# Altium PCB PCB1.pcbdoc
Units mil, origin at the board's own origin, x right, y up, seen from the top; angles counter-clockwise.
Board outline 2142.5 x 2720 mil, 2 copper layers (Top Layer, Bottom Layer); 27 components, 29 nets, 158 pads, 29 vias.
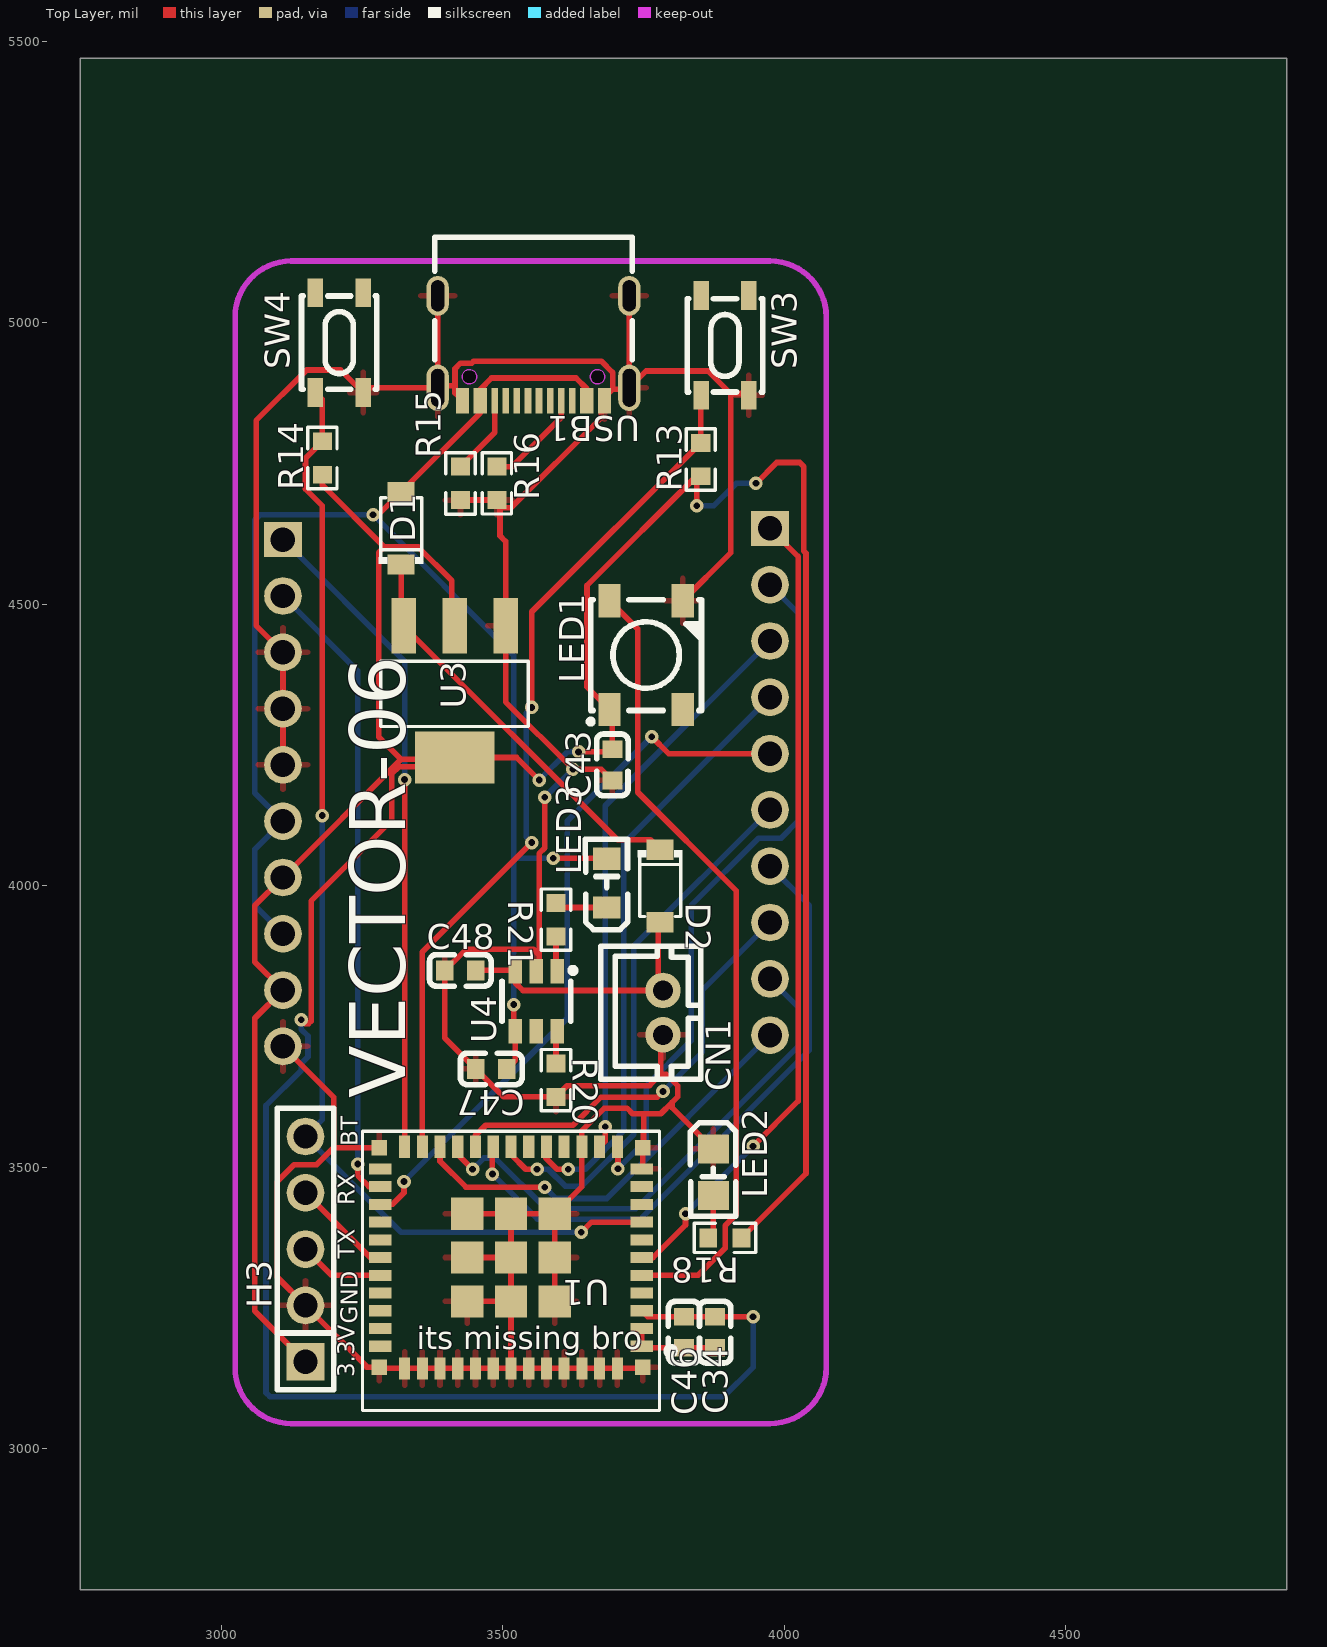
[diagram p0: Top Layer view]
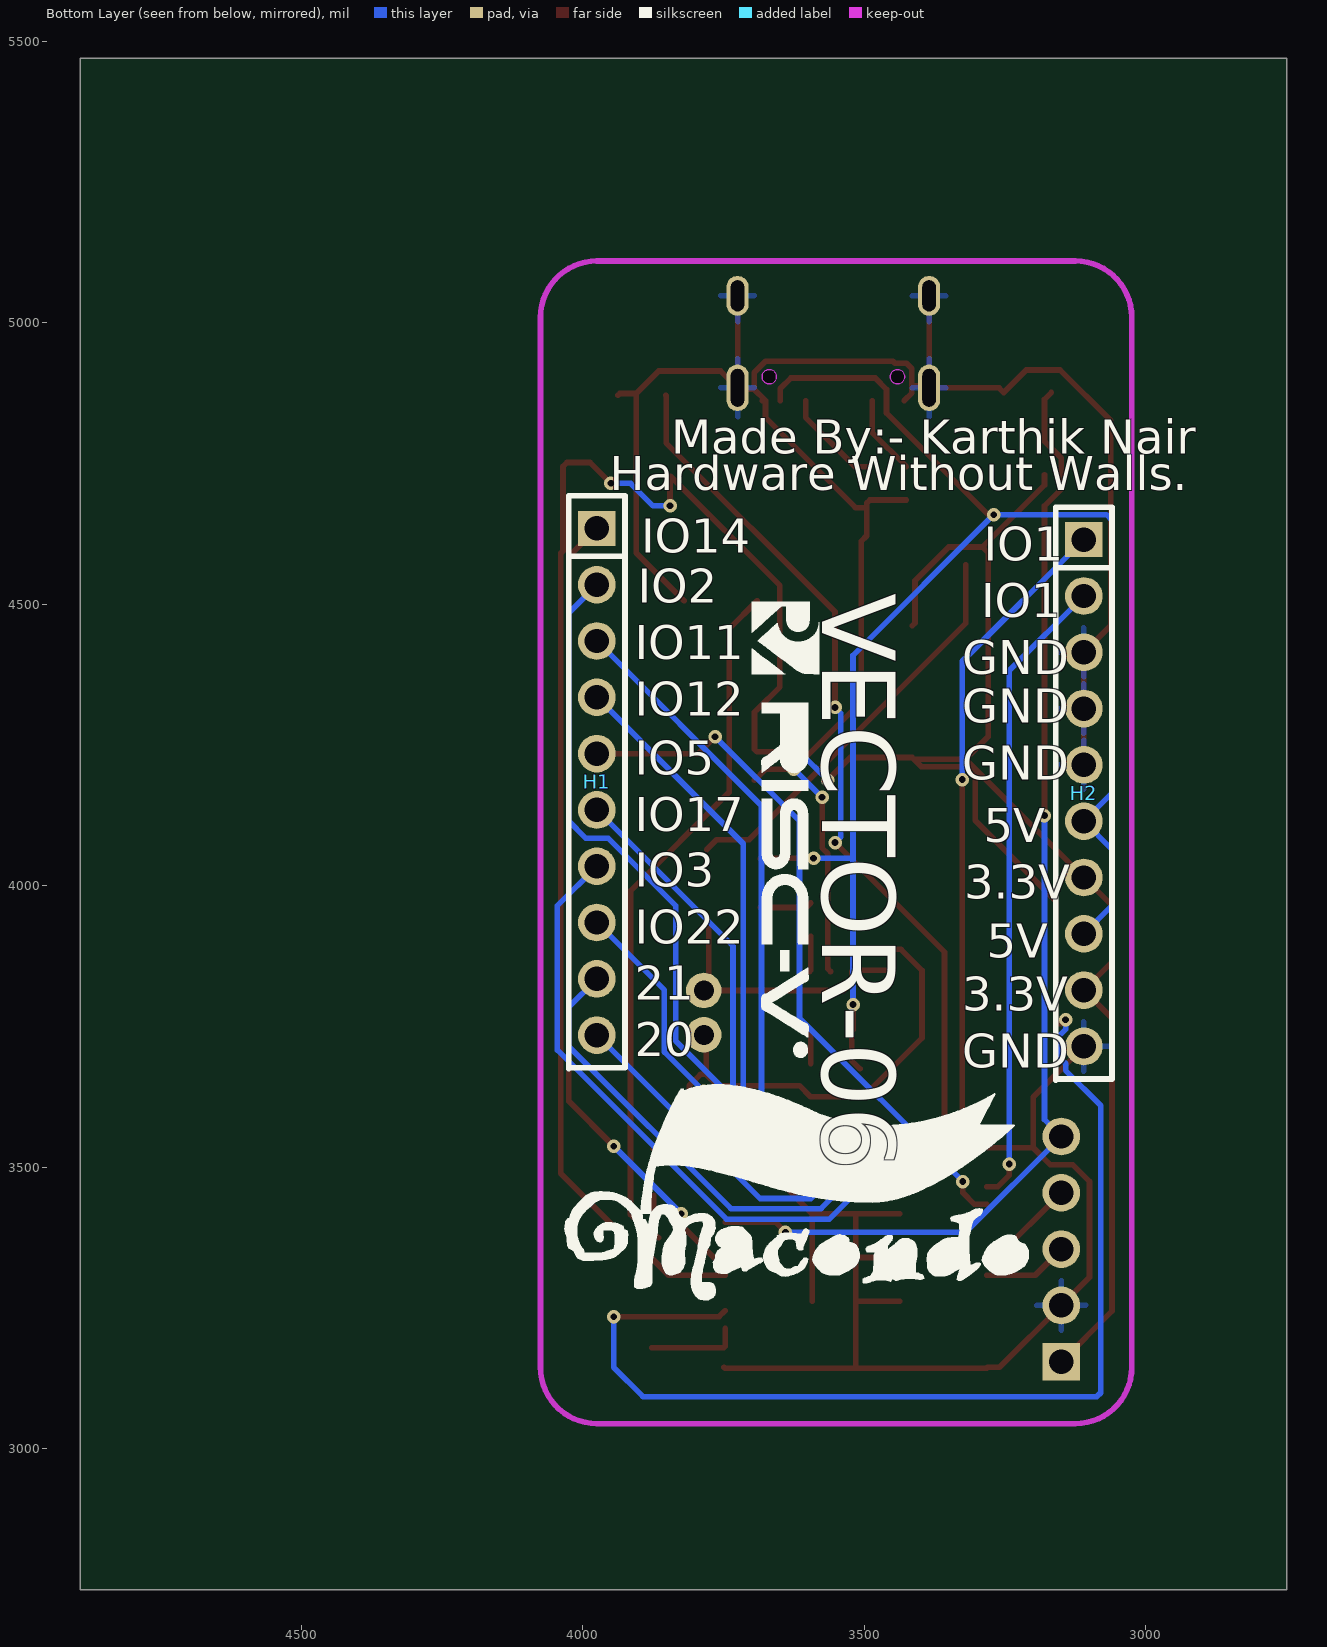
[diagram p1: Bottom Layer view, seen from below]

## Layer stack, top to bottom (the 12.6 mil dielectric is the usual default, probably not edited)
Top Layer: signal copper (thickness not stored)
Dielectric: dielectric 12.6, FR-4, Dk 4.8
Bottom Layer: signal copper (thickness not stored)

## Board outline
4892.5,2750 2750,2750 2750,5470 4892.5,5470

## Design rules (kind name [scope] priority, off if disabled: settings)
BoardOutlineClearance copperThickness1oz [All] p0: genericclearance=10 ignorepadtopadclearanceinfootprint=FALSE except(0: Arc-SplitContinuation Track-SplitContinuation SMDPad-SplitContinuation THPad-SplitContinuation Via-SplitContinuation Fill-SplitContinuation Poly-SplitContinuation Region-SplitContinuation Text-SplitContinuation; 6: Track-CutoutEdge SMDPad-CutoutEdge THPad-CutoutEdge Via-CutoutEdge Region-CutoutEdge; 11.8: Track-OutlineEdge SMDPad-OutlineEdge THPad-OutlineEdge Via-OutlineEdge Fill-OutlineEdge Region-OutlineEdge Poly-OutlineEdge Text-OutlineEdge Fill-CutoutEdge)
BoardOutlineClearance copperThickness2oz [All] p0: genericclearance=10 ignorepadtopadclearanceinfootprint=FALSE except(0: Arc-SplitContinuation Track-SplitContinuation SMDPad-SplitContinuation THPad-SplitContinuation Via-SplitContinuation Fill-SplitContinuation Poly-SplitContinuation Region-SplitContinuation Text-SplitContinuation; 6: Track-CutoutEdge SMDPad-CutoutEdge THPad-CutoutEdge Via-CutoutEdge Region-CutoutEdge; 11.8: Track-OutlineEdge SMDPad-OutlineEdge THPad-OutlineEdge Via-OutlineEdge Fill-OutlineEdge Region-OutlineEdge Poly-OutlineEdge Text-OutlineEdge Fill-CutoutEdge)
Clearance copperThickness1oz [(InNet('$1N1250') OR InNet('VCC') OR InNet('GND') OR InNet('+5V') OR InNet('IO20') OR InNet('IO21') OR InNet('IO22') OR InNet('IO3') OR InNet('IO17') OR InNet('IO5') OR InNet('IO12') OR InNet('IO11') OR InNet('IO2') OR InNet('IO14') OR InNet('IO1') OR InNet('IO0') OR InNet('TXD') OR InNet('RXD') OR InNet('BOOT_PIN') OR InNet('LED_PIN_RGB') OR InNet('$1N5981') OR InNet('NRST') OR InNet('$1N2534') OR InNet('$1N2536') OR InNet('V_REG_IN') OR InNet('BAT+') OR InNet('$1N8604') OR InNet('$1N8891') OR InNet('$1N8602'))] p1: gap=7 ignorepadtopadclearanceinfootprint=FALSE except(4: Track-Track; 6: Track-SMDPad SMDPad-SMDPad Track-THPad SMDPad-THPad THPad-THPad Track-Via SMDPad-Via THPad-Via Via-Via SMDPad-Fill THPad-Fill Via-Fill Fill-Fill Track-Region SMDPad-Region THPad-Region Via-Region Region-Region Track-Poly SMDPad-Poly THPad-Poly Via-Poly Fill-Poly Region-Poly Poly-Poly Track-Text SMDPad-Text THPad-Text Via-Text Fill-Text Region-Text Poly-Text Text-Text; 6.9: Track-Hole SMDPad-Hole THPad-Hole Via-Hole Fill-Hole Region-Hole Poly-Hole Text-Hole Sheet-Hole; 11.8: Track-Fill Fill-Region Track-Sheet SMDPad-Sheet THPad-Sheet Via-Sheet Fill-Sheet Region-Sheet Poly-Sheet Text-Sheet)
Clearance copperThickness2oz [All] p1: gap=7 ignorepadtopadclearanceinfootprint=FALSE except(6: Track-SMDPad SMDPad-SMDPad Track-THPad SMDPad-THPad THPad-THPad Track-Via SMDPad-Via THPad-Via Via-Via SMDPad-Fill THPad-Fill Via-Fill Fill-Fill Track-Region SMDPad-Region THPad-Region Via-Region Region-Region Track-Poly SMDPad-Poly THPad-Poly Via-Poly Fill-Poly Region-Poly Poly-Poly Track-Text SMDPad-Text THPad-Text Via-Text Fill-Text Region-Text Poly-Text Text-Text; 6.9: Track-Hole SMDPad-Hole THPad-Hole Via-Hole Fill-Hole Region-Hole Poly-Hole Text-Hole Sheet-Hole; 8: Track-Track; 11.8: Track-Fill Fill-Region Track-Sheet SMDPad-Sheet THPad-Sheet Via-Sheet Fill-Sheet Region-Sheet Poly-Sheet Text-Sheet)
DiffPairsRouting differentialPair [All] p1: maxuncoupledlength=10 minlimit=6 maxlimit=6 mostfreqgap=6 toplayer_minwidth=5 toplayer_prefwidth=10 toplayer_maxwidth=100 bottomlayer_minwidth=5 bottomlayer_prefwidth=10 bottomlayer_maxwidth=100
PasteMaskExpansion pasteMaskExpansion [All] p1: expansion=0
PlaneConnect innerPlane [All] p1: planeconnectstyle=Relief reliefexpansion=20 reliefentries=4 reliefconductorwidth=10 reliefairgap=10
PolygonConnect copperRegion [All] p1: connectstyle=Relief reliefentries=4 reliefconductorwidth=10 polygonreliefangle="90 Angle" airgapwidth=10
RoutingVias viaSize [All] p1: viastyle="Through Hole" holewidth=12.0078 minholewidth=11.811 maxholewidth=248.0314 width=24.0158 minwidth=19.685 maxwidth=393.7008
SolderMaskExpansion solderMaskExpansion [All] p1: useseparateexpansions=TRUE expansion=2 expansionbottom=2
Width copperThickness1oz [All] p1: maxlimit=100 minlimit=5 preferedwidth=10
Width copperThickness2oz [All] p1: maxlimit=100 minlimit=8 preferedwidth=10

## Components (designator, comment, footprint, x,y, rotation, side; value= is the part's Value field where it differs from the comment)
C34 "FCC0603B104K500CT" C0603 3877.5,3207.5 r270 top
C43 "FCC0603B104K500CT" C0603 3695,4215 r90 top
C46 "CGA0603X5R105K500JT" C0603 3822.5,3207.5 r90 top
C47 "TCC0603X5R475K160CT" C0603 3480,3675 r180 top
C48 "TCC0603X5R106K100CT" C0603 3425,3850 r0 top
CN1 "XY-B2B-PH-K-S" CONN-TH_B2B-PH-K-S 3785,3775 r90 top
D1 "1N5819W_C41431973" SOD-123_L2.7-W1.6-LS3.7-RD 3320,4635 r90 top
D2 "1N5819W_C41431973" SOD-123_L2.7-W1.6-LS3.7-RD 3780,4000 r270 top
H1 "2.54-1*10" HDR-TH_10P-P2.54-V-M 3975,4185 r270 bottom
H2 "2.54-1*10" HDR-TH_10P-P2.54-V-M 3110,4165 r270 bottom
H3 "2.54-1*5" HDR-TH_5P-P2.54-V-M 3150,3355 r90 top
LED1 "WS2812B-B/T" LED-SMD_4P-L5.0-W5.0-TL_WS2812B-B 3755,4410 r90 top
LED2 "YLED0805G" LED0805-FD-GREEN 3874.27,3491.65 r90 top
LED3 "YLED0805B" LED0805-RD 3685,4005 r90 top
R13 "FRC0603J103 TS" R0603 3851.97,4757.28 r90 top
R14 "FRC0603J103 TS" R0603 3180,4760 r90 top
R15 "FRC0603F5101TS" R0603 3425.29,4714.96 r90 top
R16 "FRC0603F5101TS" R0603 3490,4715 r90 top
R18 "FRC0603J331 TS" R0603 3895,3375 r180 top
R20 "FRC0603F2401TS" R0603 3595,3655 r270 top
R21 "FRC0603J102 TS" R0603 3595,3940 r270 top
SW3 "TS-1089S-02526" SW-SMD_4P-L4.2-W3.3-P2.15-LS5.1 3895,4960 r90 top
SW4 "TS-1089S-02526" SW-SMD_4P-L4.2-W3.3-P2.15-LS5.1 3210,4965 r90 top
U1 "Ai-WB2-M1-I" WIFIM-SMD_61P-CUSTOMBRUH 3515,3340 r180 top
U3 "AMS1117-3.3_C22459274" SOT-223-3_L6.5-W3.4-P2.30-LS7.0-BR-1 3415,4345 r90 top
U4 "TP4059" SOT-23-6_L2.9-W1.6-P0.95-LS2.8-BR 3560,3795 r90 top
USB1 "TYPE-C16PIN" USB-C-SMD_TYPE-C16PIN 3555,4955 r180 top

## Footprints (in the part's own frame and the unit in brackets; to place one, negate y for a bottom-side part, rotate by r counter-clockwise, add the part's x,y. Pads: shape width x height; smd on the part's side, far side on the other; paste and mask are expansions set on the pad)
C0603 [mm]
  rect 0.8x0.9 smd: 1(-0.7,0) 2(0.7,0)
  silkscreen extent -1.39,-0.71 1.39,0.71
CONN-TH_B2B-PH-K-S [mm]
  round 1.6 hole 0.9: 1(1,0) 2(-1,0)
  silkscreen extent -3,-1.7 3,2.8
HDR-TH_5P-P2.54-V-M [mm]
  rect 1.7x1.7 hole 1.1: 1(-5.08,0)
  round 1.7 hole 1.1: 2(-2.54,0) 3(0,0) 4(2.54,0) 5(5.08,0)
  silkscreen extent -6.35,-1.27 6.35,1.27
HDR-TH_10P-P2.54-V-M [mm]
  rect 1.575x1.7 hole 1.1: 1(-11.43,0)
  round 1.7 hole 1.1: 2(-8.89,0) 3(-6.35,0) 4(-3.81,0) 5(-1.27,0) 6(1.27,0) 7(3.81,0) 8(6.35,0) 9(8.89,0) 10(11.43,0)
  silkscreen extent -12.9,-1.27 12.95,1.27
LED0805-FD-GREEN [mil]
  rect 51.2x55.1 smd: 1(-41.35,0) 2(41.35,0)
  silkscreen extent -78,-40 88,41
LED0805-RD [mm]
  rect 1x1.25 smd: 1(-1.1,0) 2(1.1,0)
  silkscreen extent -2.1,-0.95 1.98,0.96
LED-SMD_4P-L5.0-W5.0-TL_WS2812B-B [mm]
  rect 1.5x1 smd: 1(-2.45,1.65) 2(-2.45,-1.65) 3(2.45,-1.65) 4(2.45,1.65)
  silkscreen extent -3.1,-2.5 2.5,2.6
R0603 [mil]
  rect 31.75x34.02 smd: 1(-29.66,0) 2(29.66,0)
  silkscreen extent -55,-26 55,26
SOD-123_L2.7-W1.6-LS3.7-RD [mm]
  rect 0.91x1.22 smd: 1(-1.635,0) 2(1.635,0)
  silkscreen extent -1.6,-1 1.38,1
SOT-23-6_L2.9-W1.6-P0.95-LS2.8-BR [mm]
  rect 1.1x0.6 smd: 1(1.35,-0.95) 2(1.35,0) 3(1.35,0.95) 4(-1.35,0.95) 5(-1.35,0) 6(-1.35,-0.95)
  silkscreen extent -0.9,-1.78 1.52,1.55
SOT-223-3_L6.5-W3.4-P2.30-LS7.0-BR-1 [mm]
  rect 2.5x1.1 smd: 1(2.97,-2.3) 2(2.97,0) 3(2.97,2.3)
  rect 2.34x3.6 smd: 2(-2.97,0)
  silkscreen extent -1.57,-3.33 1.37,3.33
SW-SMD_4P-L4.2-W3.3-P2.15-LS5.1 [mm]
  rect 1.3x0.7 smd: 1(-2.25,1.075) 2(2.25,1.075) 3(-2.25,-1.075) 4(2.25,-1.075)
  silkscreen extent -2.1,-1.7 2.1,1.7
USB-C-SMD_TYPE-C16PIN [mm]
  oval 1x2.1 hole 0.6 slot 1.7 at 90 deg: 1(-4.32,1.787) 2(4.32,1.787)
  oval 1x1.8 hole 0.6 slot 1.4 at 90 deg: 3(-4.32,-2.362) 4(4.32,-2.362)
  rect 0.6x1.15 smd: A1B12(-3.2,2.362) A4B9(-2.4,2.362) B1A12(3.2,2.362) B4A9(2.4,2.362)
  rect 0.3x1.15 smd: A5(-1.25,2.362) A6(-0.25,2.362) A7(0.25,2.362) A8(1.25,2.362) B5(1.75,2.362) B6(0.75,2.362) B7(-0.75,2.362) B8(-1.75,2.362)
  Board Outline Layer circle w0.005: c2.89,1.288 r0.325
  Board Outline Layer circle w0.005: c-2.89,1.288 r0.325
  Board Outline Layer region: 2.565,1.288 2.597,1.429 2.687,1.542 2.818,1.605 2.962,1.605 3.093,1.542 3.183,1.429 3.215,1.288 3.215,1.288 3.183,1.147 3.093,1.034 2.962,0.971 2.818,0.971 2.687,1.034 2.597,1.147 2.565,1.288
  Board Outline Layer region: -3.215,1.288 -3.183,1.429 -3.093,1.542 -2.962,1.605 -2.818,1.605 -2.687,1.542 -2.597,1.429 -2.565,1.288 -2.565,1.288 -2.597,1.147 -2.687,1.034 -2.818,0.971 -2.962,0.971 -3.093,1.034 -3.183,1.147 -3.215,1.288
  Multi-Layer board cut-out: 2.565,1.288 2.597,1.429 2.687,1.542 2.818,1.605 2.962,1.605 3.093,1.542 3.183,1.429 3.215,1.288 3.215,1.288 3.183,1.147 3.093,1.034 2.962,0.971 2.818,0.971 2.687,1.034 2.597,1.147 2.565,1.288
  Multi-Layer board cut-out: -3.215,1.288 -3.183,1.429 -3.093,1.542 -2.962,1.605 -2.818,1.605 -2.687,1.542 -2.597,1.429 -2.565,1.288 -2.565,1.288 -2.597,1.147 -2.687,1.034 -2.818,0.971 -2.962,0.971 -3.093,1.034 -3.183,1.147 -3.215,1.288
  silkscreen extent -4.45,-5 4.45,0.52
WIFIM-SMD_61P-CUSTOMBRUH [mm]
  rect 1x0.5 smd: 1(-5.9,4) 2(-5.9,3.2) 3(-5.9,2.4) 4(-5.9,1.6) 5(-5.9,0.8) 6(-5.9,0) 7(-5.9,-0.8) 8(-5.9,-1.6) 9(-5.9,-2.4) 10(-5.9,-3.2) 11(-5.9,-4) 25(5.9,-4) 26(5.9,-3.2) 27(5.9,-2.4) 28(5.9,-1.6) 29(5.9,-0.8) 30(5.9,0) 31(5.9,0.8) 32(5.9,1.6) 33(5.9,2.4) 34(5.9,3.2) 35(5.9,4)
  rect 0.5x1 smd: 12(-4.8,-5) 13(-4,-5) 14(-3.2,-5) 15(-2.4,-5) 16(-1.6,-5) 17(-0.8,-5) 18(0,-5) 19(0.8,-5) 20(1.6,-5) 21(2.4,-5) 22(3.2,-5) 23(4,-5) 24(4.8,-5) 36(4.8,5) 37(4,5) 38(3.2,5) 39(2.4,5) 40(1.6,5) 41(0.8,5) 42(0,5) 43(-0.8,5) 44(-1.6,5) 45(-2.4,5) 46(-3.2,5) 47(-4,5) 48(-4.8,5)
  rect 1.45x1.45 smd: 49(0,0) 54(-1.975,0) 55(-1.975,1.975) 56(0,1.975) 57(1.975,1.975) 58(1.975,0) 59(-1.975,-1.975) 60(0,-1.975) 61(1.975,-1.975)
  rect 0.7x0.7 smd: 50(5.95,4.95) 51(5.95,-4.95) 52(-5.95,-4.95) 53(-5.95,4.95)
  silkscreen extent -7.4,-5.7 6.7,6.9

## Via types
v1: diameter 24.02, hole 12.01, Top Layer to Bottom Layer, 29 vias

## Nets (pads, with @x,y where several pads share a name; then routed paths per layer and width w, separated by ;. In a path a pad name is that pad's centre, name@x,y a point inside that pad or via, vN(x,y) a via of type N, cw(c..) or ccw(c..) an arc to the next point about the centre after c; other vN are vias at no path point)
$1N1250: C34.2 C46.1 U1.1 U1.2 | length 162.8
  Top Layer w10: U1.2 U1.1 3749.86,3179.94 C46.1 C34.2
$1N2534: R15.2 USB1.B5 | length 142.6
  Top Layer w10: R15.2 3486.1,4805.43 USB1.B5
$1N2536: R16.2 USB1.A5 | length 180.4
  Top Layer w10: R16.2 3516.88,4744.66 3604.21,4831.99 USB1.A5
$1N5981: LED2.1 R18.2 | length 79
  Top Layer w10: R18.2 3874.27,3383.93 LED2.1
$1N8602: R21.2 U4.1 | length 63.2
  Top Layer w10: R21.2 3595,3850.55 U4.1
$1N8604: LED3.1 R21.1 | length 93.3
  Top Layer w10: R21.1 3602.97,3961.69 LED3.1
$1N8891: R20.1 U4.6 | length 58.2
  Top Layer w10: R20.1 3595,3739.45 U4.6
+5V: C47.1 D1.2 H2.6 H2.8 LED3.2 U4.4 USB1.A4B9 USB1.B4A9 | length 2804.9
  Top Layer w10: v1(3270,4659.37) 3280,4659.37 D1.2 3460.51,4839.88 USB1.B4A9 3460.51,4881.99 3480.51,4901.99 3630.51,4901.99 3649.49,4883.01 USB1.A4B9 ; C47.1 3522.6,3690.04 U4.4 3520,3744.45 v1(3520,3789.37) ; v1(3590,4049.37) 3683.93,4049.37 LED3.2
  Bottom Layer w10: H2.8 3060,3965 3060,4065 H2.6 3060,4165 3060,4649.37 3070,4659.37 v1(3270,4659.37) 3520,4409.37 3520,4049.37 ; v1(3520,3789.37) 3520,4049.37 ; v1(3590,4049.37) 3520,4049.37
BAT+: C48.2 CN1.1 D2.2 U4.3 | length 481.7
  Top Layer w10: C48.2 3520.75,3850 U4.3 3522.6,3828.15 3536.38,3814.37 CN1.1@3776.38,3814.37 ; D2.2 3776.38,3932.01 CN1.1@3776.38,3814.37 ; CN1.1 CN1.1@3776.38,3814.37
BOOT_PIN: H3.5 R14.2 SW4.1 U1.8 | length 2039
  Top Layer w10: SW4.1 3180,4864.09 R14.2 3150,4759.66 3150,4705 3180,4675 v1(3180,4125) ; v1(3640,3385) 3657.99,3402.99 U1.8
  Bottom Layer w10: v1(3180,4125) 3180,3585 H3.5 3320,3385 v1(3640,3385)
GND: C43.1 C47.2 C48.1 CN1.2 H2.3 H2.4 H2.5 H2.10 H3.2 LED1.3 LED2.2 R15.1 R16.1 R20.2 SW3.3 SW4.3 U1.11 U1.14 U1.36 U1.37 U1.38 U1.39 U1.40 U1.41 U1.42 U1.43 U1.44 U1.45 U1.46 U1.47 U1.48 U1.49 U1.50 U1.51 U1.52 U1.53 U1.54 U1.55 U1.56 U1.57 U1.58 U1.59 U1.60 U1.61 U3.1 U4.2 USB1.1 USB1.2 USB1.3 USB1.4 USB1.A1B12 USB1.B1A12 | length 7320.3
  Top Layer w10: H2.10 3200,3625 3200,3535 ; H2.5 H2.4 H2.3 3062.32,4462.68 3062.32,4826.42 3152.32,4916.42 3212.32,4916.42 SW4.3 3260.54,4884.63 USB1.2 ; U1.51@3280.62,3535 3200,3535 ; USB1.4 USB1.2 ; R15.1 R16.1 3495.55,4679.79 R16.1@3495.55,4671.93 ; USB1.B1A12 3415.55,4875.46 3415.55,4888.52 ; U1.57 U1.56 ; U1.58 U1.49 ; U1.61 U1.60 ; U4.2 3565,3853.15 3565,3877.44 ; v1(3575,4157.44) 3575,4067.44 3565,4057.44 3565,3877.44 ; U1.55@3592.75,3262.26 U1.54 U1.59 ; USB1.A1B12 USB1.A1B12@3675.55,4861.93 ; C43.1 3675,4207.44 v1(3625,4207.44) 3505.55,4326.89 U3.1 3505.55,4611.93 3495.55,4621.93 R16.1@3495.55,4671.93 ; USB1.3 USB1.1 ; U1.11 3749.25,3499.45 U1.52 3750.98,3536.61 3750.98,3595.34 ; U1.53 3747.28,3143.14 U1.48 U1.47 U1.46 U1.45 U1.44 U1.43 U1.42 ; CN1.2 3780.98,3731.61 3780.98,3665.34 ; LED1.3 3905.08,4591.57 3905.08,4874.63 ; LED2.2 3800.98,3606.3 3800.98,3615.34 ; SW3.3 3934.11,4874.63 3905.08,4874.63 ; 3200,3535 3170,3505 3130,3505 3100,3475 3100,3305 H3.2 3259.89,3145.11 U1.50 3282.72,3143.14 U1.36 U1.37 U1.38 U1.39 U1.40 U1.41 U1.42 ; USB1.2 3388.81,4888.52 3415.55,4888.52 ; 3415.55,4888.52 3415.55,4918.52 3425.55,4928.52 3445.55,4928.52 3448.95,4931.93 3675.55,4931.93 3695.55,4911.93 3695.55,4881.93 ; R16.1@3495.55,4671.93 3515.55,4671.93 3675.55,4831.93 USB1.A1B12@3675.55,4861.93 ; U1.42 U1.56 ; U1.56 U1.49 ; U1.49 U1.60 ; U1.60 U1.59 ; 3565,3877.44 3555,3887.44 3434.88,3887.44 C48.1 3397.44,3730 C47.2 3502.1,3625.34 R20.2 3615,3645.34 3760.98,3645.34 3780.98,3665.34 ; U1.59 3640.98,3465.99 U1.14 3640.98,3565.34 3680.98,3605.34 3720.98,3605.34 3730.98,3595.34 3750.98,3595.34 ; USB1.A1B12@3675.55,4861.93 3695.55,4881.93 ; 3695.55,4881.93 3722.38,4881.93 USB1.1 ; USB1.1 3755.08,4914.63 3865.08,4914.63 3905.08,4874.63 ; 3750.98,3595.34 3780.98,3595.34 3800.98,3615.34 ; 3780.98,3665.34 3790.98,3665.34 3810.98,3645.34 3810.98,3625.34 3800.98,3615.34
  Bottom Layer w10: v1(3575,4157.44) v1(3625,4207.44)
IO0: H2.1 U1.24 | length 1167.6
  Top Layer w10: U1.24 v1(3326.02,4188.98)
  Bottom Layer w10: H2.1 3326.02,4398.98 v1(3326.02,4188.98)
IO1: H2.2 U1.26 | length 1132.3
  Top Layer w10: v1(3242.72,3505.99) 3242.72,3485.99 3262.72,3465.99 U1.26
  Bottom Layer w10: H2.2 3242.72,4382.28 v1(3242.72,3505.99)
IO2: H1.2 U1.12 | length 1253.2
  Top Layer w10: U1.12 3705,3535.83 v1(3705,3497.88)
  Bottom Layer w10: v1(3705,3497.88) 3755,3547.88 3755,3645 3835,3725 3835,3965 3955,4085 3995,4085 4025,4115 4025,4485 H1.2
IO3: H1.7 U1.19 | length 1125.2
  Top Layer w10: v1(3482,3488.36) 3482,3535.35 U1.19
  Bottom Layer w10: v1(3482,3488.36) 3562,3408.36 3745,3408.36 4045,3708.36 4045,3965 H1.7
IO5: H1.5 U1.27 | length 1265.5
  Top Layer w10: U1.27 3283.23,3435 3305,3435 3325,3455 v1(3325,3475) ; v1(3765,4265) 3795,4235 H1.5
  Bottom Layer w10: v1(3325,3475) 3615,3765 3615,4115 v1(3765,4265)
IO11: H1.3 U1.13 | length 1023.5
  Top Layer w10: U1.13 3682.48,3546.86 v1(3682.48,3572.48)
  Bottom Layer w10: v1(3682.48,3572.48) 3682.48,4142.48 H1.3
IO12: H1.4 U1.16 | length 1072.8
  Top Layer w10: U1.16 3576.86,3535.72 3576.86,3516.86 3596.86,3496.86 v1(3616.86,3496.86)
  Bottom Layer w10: v1(3616.86,3496.86) 3646.86,3496.86 3715,3565 3715,4075 H1.4
IO14: H1.1 U1.6 | length 1442.5
  Top Layer w10: U1.6 3767.28,3340.01 3825,3397.73 v1(3825,3417.73) ; v1(3945,3537.73) 4025,3617.73 4025,4585 H1.1
  Bottom Layer w10: v1(3825,3417.73) v1(3945,3537.73)
IO17: H1.6 U1.18 | length 969.7
  Top Layer w10: U1.18 3515,3523.14 3541.29,3496.86 v1(3561.29,3496.86)
  Bottom Layer w10: v1(3561.29,3496.86) 3581.29,3496.86 3611.29,3466.86 3641.29,3466.86 3733.14,3558.71 3733.14,3893.14 H1.6
IO20: H1.10 U1.22 | length 759.3
  Top Layer w10: U1.22 3389.01,3510.99 3435,3465 v1(3575,3465)
  Bottom Layer w10: v1(3575,3465) 3595,3445 3685,3445 H1.10
IO21: H1.9 U1.21 | length 934.7
  Top Layer w10: U1.21 3420.51,3523.2 v1(3446.86,3496.86)
  Bottom Layer w10: v1(3446.86,3496.86) 3466.86,3516.86 3486.86,3516.86 3576.86,3426.86 3736.86,3426.86 4025,3715 4025,3785 H1.9
IO22: H1.8 U1.20 | length 764.1
  Top Layer w10: U1.20 3452.01,3556.86 3470.15,3575 3625,3575 3675,3625 3775,3625 v1(3785,3635)
  Bottom Layer w10: v1(3785,3635) 3855,3705 3855,3815 H1.8
LED_PIN_RGB: LED1.4 U1.5 | length 1419.4
  Top Layer w10: LED1.4 3740.04,4456.45 3740.04,4166.45 3915.23,3991.27 3915.23,3416.45 3895.23,3396.45 3895.23,3356.45 3847.28,3308.51 U1.5
NRST: R13.2 SW3.1 U1.23 | length 1547.9
  Top Layer w10: U1.23 3357.52,3882.49 v1(3551.97,4076.94) ; v1(3551.97,4316.94) 3551.97,4486.94 R13.2 3851.97,4870.71 SW3.1
  Bottom Layer w10: v1(3551.97,4076.94) 3541.97,4086.94 3541.97,4306.94 v1(3551.97,4316.94)
RXD: H3.4 U1.30 | length 180.4
  Top Layer w10: H3.4 3264.99,3340.01 U1.30
TXD: H3.3 U1.31 | length 152
  Top Layer w10: H3.3 3196.49,3308.51 U1.31
V_REG_IN: D1.1 D2.1 U3.3 | length 730.8
  Top Layer w10: D1.1 3320,4466.38 U3.3 3704.45,4081.93 3762.45,4081.93 D2.1
VCC: C34.1 C43.2 C46.2 H2.7 H2.9 H3.1 LED1.1 R13.1 R14.1 R18.1 U1.3 U3.2 | length 7281.2
  Top Layer w10: v1(3142.5,3762.5) 3149.39,3755.61 3155.61,3755.61 3160,3760 3160,3973.07 3303.03,4116.1 3303.03,4198.51 3316.49,4211.97 3398.9,4211.97 U3.2@3411.93,4225 ; H3.1 3060,3245 3060,3765 H2.9 3060,3865 3060,3965 H2.7 3320,4225 ; R14.1 3180,4711.93 3290,4601.93 ; U3.2@3415,4461.93 3410,4466.93 3410,4541.93 3350,4601.93 3290,4601.93 ; v1(3565,4188.07) 3525,4228.07 3415,4228.07 U3.2@3411.93,4225 ; v1(3635,4238.07) 3690.51,4238.07 C43.2 3695,4308.59 LED1.1 3650.04,4353.55 3650.04,4533.55 3844.11,4727.62 R13.1 3845,4720.65 v1(3845,4675) ; U1.3 3757.73,3235.06 C46.2 C34.1 ; C34.1@3877.56,3235 v1(3945,3235) ; R18.1 4039.02,3489.36 4039.02,4590.81 4035,4594.82 4035,4745 4027.93,4752.07 3987.07,4752.07 v1(3950,4715) ; 3290,4601.93 3280,4591.93 3280,4265 3320,4225 ; 3320,4225 U3.2@3411.93,4225
  Bottom Layer w10: v1(3142.5,3762.5) 3142.5,3745.36 3154.45,3733.41 3154.45,3696.59 3142.5,3684.64 3142.5,3672.5 3080,3610 3080,3100 3087.07,3092.93 3892.93,3092.93 3945,3145 v1(3945,3235) ; v1(3565,4188.07) 3615,4238.07 v1(3635,4238.07) ; v1(3845,4675) 3875,4675 3915,4715 v1(3950,4715)
pads on no net: LED1.2 SW3.2 SW3.4 SW4.2 SW4.4 U1.4 U1.7 U1.9 U1.10 U1.15 U1.17 U1.25 U1.28 U1.29 U1.32 U1.33 U1.34 U1.35 U4.5 USB1.A6 USB1.A7 USB1.A8 USB1.B6 USB1.B7 USB1.B8

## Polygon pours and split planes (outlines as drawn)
GND on Top Layer (solid, remove dead copper, pour order 0): 3025,3035 3025,5165 4150,5165 4150,3035
GND on Bottom Layer (solid, remove dead copper, pour order 2): 3000,3000 3000,5220 4175,5220 4175,3000

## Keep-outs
Board Outline Layer:
  lines w10: 3025,3145 3025,5010 cw(c3125,5010) 3125,5110 3975,5110 cw(c3975,5010) 4075,5010 4075,3145 cw(c3975,3145) 3975,3045 3125,3045 cw(c3125,3145) 3025,3145

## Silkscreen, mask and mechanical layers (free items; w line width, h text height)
Top Silkscreen Layer:
  text "VECTOR-06" at 3327.5,3622.5 h100 r90
  text "BT" at 3242.5,3537.5 h30 r90
  text "RX" at 3237.5,3432.5 h30 r90
  text "TX" at 3237.5,3337.5 h30 r90
  text "GND" at 3242.5,3222.5 h30 r90
  text "its missing bro" at 3347.5,3177.5 h40
  text "3.3V" at 3237.5,3127.5 h30 r90
Bottom Silkscreen Layer:
  drawing of 25 lines, arcs and shapes, not listed
  text "Made By:- Karthik Nair" at 3842.5,4767.5 h60
  text "Hardware Without Walls." at 3952.5,4702.5 h60
  text "IO14" at 3895.95,4591.57 h60
  text "IO1" at 3287.82,4577.82 h60
  text "VECTOR-06" at 3574.83,4519.89 h130 r90
  text "IO2" at 3902.5,4502.5 h60
  text "IO1" at 3292.5,4477.5 h60
  text "IO11" at 3907.5,4402.5 h60
  text "GND" at 3326.02,4376.3 h60
  text "IO12" at 3907.5,4302.5 h60
  text "GND" at 3326.02,4289.74 h60
  text "IO5" at 3907.5,4197.5 h60
  text "GND" at 3326.02,4188.98 h60
  text "IO17" at 3907.5,4097.5 h60
  text "5V" at 3287.5,4077.5 h60
  text "IO3" at 3907.56,3998.94 h60
  text "3.3V" at 3322.5,3977.5 h60
  text "IO22" at 3907.5,3897.5 h60
  text "5V" at 3282.5,3872.5 h60
  text "21" at 3907.5,3797.5 h60
  text "3.3V" at 3326.02,3778.17 h60
  text "20" at 3907.5,3697.5 h60
  text "GND" at 3326.02,3677.07 h60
